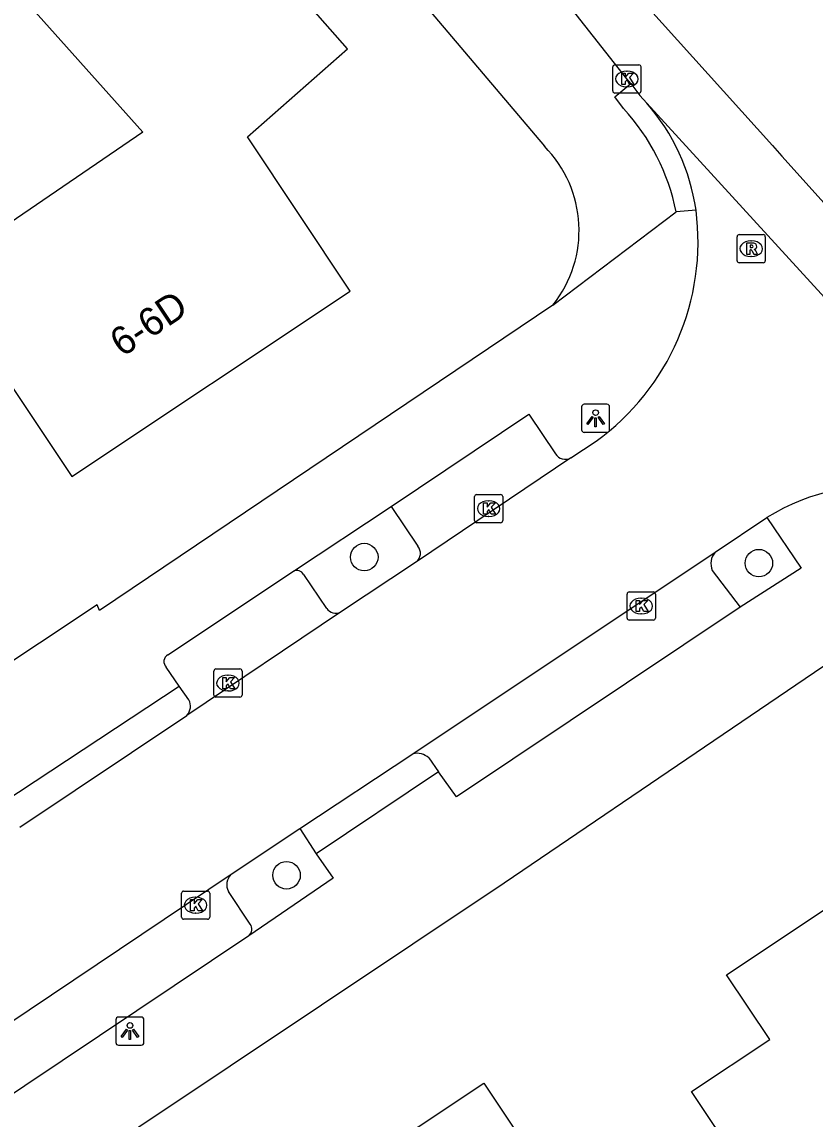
# Model space of a CAD drawing. Extents: x 161354 to 161876, y 382161 to 382804.
# Drawn here: x 161609.6 to 161637.75, y 382619.62 to 382658.57 of the extents above; entities that cross this region are included whole.
import ezdxf

# ---------------------------------------------------------------- set-up
doc = ezdxf.new("R2010")
doc.units = 0
for name, color, linetype in [('IMGEO_Boom', 7, 'Continuous'), ('IMGEO_Fietspad_gesloten', 7, 'Continuous'), ('IMGEO_Kolk', 7, 'Continuous'), ('IMGEO_Lichtpunt', 7, 'Continuous'), ('IMGEO_Pand', 7, 'Continuous'), ('IMGEO_Pand_nummerreeks', 7, 'Continuous'), ('IMGEO_Parkeervlak_open', 7, 'Continuous'), ('IMGEO_Rijbaan_lokaal_gesloten', 7, 'Continuous'), ('IMGEO_Rijbaan_lokaal_open', 7, 'Continuous'), ('IMGEO_Rioolput', 7, 'Continuous'), ('IMGEO_Voetpad_open', 7, 'Continuous')]:
    doc.layers.add(name, color=color, linetype=linetype)

msp = doc.modelspace()

# ---------------------------------------------------------------- linework, layer by layer
at = {"layer": 'IMGEO_Boom'}
for centre in [(161621.754, 382639.57), (161635.76, 382639.355), (161618.995, 382628.273)]:
    msp.add_circle(centre, 0.489, dxfattribs=at)
at = {"layer": 'IMGEO_Fietspad_gesloten'}
for points in [[(161631.214, 382656.385), (161631.077, 382656.546), (161628.402, 382659.955), (161626.262, 382662.585), (161622.699, 382666.884), (161617.707, 382672.442), (161614.343, 382676.276)], [(161631.214, 382656.385), (161631.541, 382655.956), (161631.782, 382655.692)]]:
    msp.add_lwpolyline(points, dxfattribs=at)
at = {"layer": 'IMGEO_Kolk'}
for p, q in [((161630.576, 382656.12), (161630.576, 382656.972)), ((161630.651, 382657.046), (161631.503, 382657.046)), ((161631.064, 382656.826), (161631.089, 382656.826)), ((161631.577, 382656.972), (161631.577, 382656.12)), ((161631.503, 382656.046), (161630.651, 382656.046)), ((161631.087, 382656.266), (161631.062, 382656.266)), ((161625.669, 382640.865), (161625.669, 382641.717)), ((161625.744, 382641.791), (161626.596, 382641.791)), ((161626.157, 382641.571), (161626.182, 382641.571)), ((161626.67, 382641.717), (161626.67, 382640.865)), ((161626.596, 382640.791), (161625.744, 382640.791)), ((161626.18, 382641.011), (161626.155, 382641.011)), ((161631.085, 382637.407), (161631.085, 382638.259)), ((161631.16, 382638.333), (161632.012, 382638.333)), ((161631.573, 382638.113), (161631.598, 382638.113)), ((161632.086, 382638.259), (161632.086, 382637.407)), ((161632.012, 382637.333), (161631.16, 382637.333)), ((161631.596, 382637.553), (161631.571, 382637.553)), ((161616.415, 382634.671), (161616.415, 382635.523)), ((161616.49, 382635.597), (161617.342, 382635.597)), ((161616.903, 382635.377), (161616.928, 382635.377)), ((161617.416, 382635.523), (161617.416, 382634.671)), ((161617.342, 382634.597), (161616.49, 382634.597)), ((161616.926, 382634.817), (161616.901, 382634.817)), ((161615.268, 382626.786), (161615.268, 382627.638)), ((161615.343, 382627.712), (161616.195, 382627.712)), ((161616.269, 382627.638), (161616.269, 382626.786)), ((161615.756, 382627.492), (161615.781, 382627.492)), ((161615.779, 382626.932), (161615.754, 382626.932)), ((161616.195, 382626.712), (161615.343, 382626.712))]:
    msp.add_line(p, q, dxfattribs=at)
for points in [[(161630.576, 382656.12), (161630.576, 382656.972)], [(161630.651, 382657.046), (161631.503, 382657.046)], [(161630.897, 382656.746), (161631.02, 382656.746), (161631.02, 382656.595), (161631.15, 382656.746), (161631.314, 382656.746), (161631.168, 382656.595), (161631.321, 382656.346), (161631.169, 382656.346), (161631.084, 382656.51), (161631.02, 382656.443), (161631.02, 382656.346), (161630.897, 382656.346), (161630.897, 382656.746)], [(161631.577, 382656.972), (161631.577, 382656.12)], [(161631.503, 382656.046), (161630.651, 382656.046)], [(161625.669, 382640.865), (161625.669, 382641.717)], [(161625.744, 382641.791), (161626.596, 382641.791)], [(161626.67, 382641.717), (161626.67, 382640.865)], [(161625.99, 382641.491), (161626.113, 382641.491), (161626.113, 382641.34), (161626.243, 382641.491), (161626.407, 382641.491), (161626.261, 382641.34), (161626.414, 382641.091), (161626.262, 382641.091), (161626.177, 382641.255), (161626.113, 382641.188), (161626.113, 382641.091), (161625.99, 382641.091), (161625.99, 382641.491)], [(161626.596, 382640.791), (161625.744, 382640.791)], [(161631.085, 382637.407), (161631.085, 382638.259)], [(161631.16, 382638.333), (161632.012, 382638.333)], [(161632.086, 382638.259), (161632.086, 382637.407)], [(161631.406, 382638.033), (161631.529, 382638.033), (161631.529, 382637.882), (161631.659, 382638.033), (161631.823, 382638.033), (161631.677, 382637.882), (161631.83, 382637.633), (161631.678, 382637.633), (161631.593, 382637.797), (161631.529, 382637.73), (161631.529, 382637.633), (161631.406, 382637.633), (161631.406, 382638.033)], [(161632.012, 382637.333), (161631.16, 382637.333)], [(161616.415, 382634.671), (161616.415, 382635.523)], [(161616.49, 382635.597), (161617.342, 382635.597)], [(161617.416, 382635.523), (161617.416, 382634.671)], [(161616.736, 382635.297), (161616.859, 382635.297), (161616.859, 382635.146), (161616.989, 382635.297), (161617.153, 382635.297), (161617.007, 382635.146), (161617.16, 382634.897), (161617.008, 382634.897), (161616.923, 382635.061), (161616.859, 382634.994), (161616.859, 382634.897), (161616.736, 382634.897), (161616.736, 382635.297)], [(161617.342, 382634.597), (161616.49, 382634.597)], [(161615.268, 382626.786), (161615.268, 382627.638)], [(161615.343, 382627.712), (161616.195, 382627.712)], [(161616.269, 382627.638), (161616.269, 382626.786)], [(161615.589, 382627.412), (161615.712, 382627.412), (161615.712, 382627.261), (161615.842, 382627.412), (161616.006, 382627.412), (161615.86, 382627.261), (161616.013, 382627.012), (161615.861, 382627.012), (161615.776, 382627.176), (161615.712, 382627.109), (161615.712, 382627.012), (161615.589, 382627.012), (161615.589, 382627.412)], [(161616.195, 382626.712), (161615.343, 382626.712)]]:
    msp.add_lwpolyline(points, dxfattribs=at)
for centre, start, end in [((161630.653, 382656.97), 91.552, 178.448), ((161630.653, 382656.97), 91.552, 178.448), ((161631.501, 382656.97), 1.552, 88.448), ((161631.501, 382656.97), 1.552, 88.448), ((161630.653, 382656.122), 181.552, 268.448), ((161630.653, 382656.122), 181.552, 268.448), ((161631.501, 382656.122), 271.552, 358.448), ((161631.501, 382656.122), 271.552, 358.448), ((161625.746, 382641.715), 91.552, 178.448), ((161625.746, 382641.715), 91.552, 178.448), ((161626.594, 382641.715), 1.552, 88.448), ((161626.594, 382641.715), 1.552, 88.448), ((161625.746, 382640.867), 181.552, 268.448), ((161625.746, 382640.867), 181.552, 268.448), ((161626.594, 382640.867), 271.552, 358.448), ((161626.594, 382640.867), 271.552, 358.448), ((161631.162, 382638.257), 91.552, 178.448), ((161631.162, 382638.257), 91.552, 178.448), ((161632.01, 382638.257), 1.552, 88.448), ((161632.01, 382638.257), 1.552, 88.448), ((161631.162, 382637.409), 181.552, 268.448), ((161631.162, 382637.409), 181.552, 268.448), ((161632.01, 382637.409), 271.552, 358.448), ((161632.01, 382637.409), 271.552, 358.448), ((161616.492, 382635.521), 91.552, 178.448), ((161616.492, 382635.521), 91.552, 178.448), ((161617.34, 382635.521), 1.552, 88.448), ((161617.34, 382635.521), 1.552, 88.448), ((161616.492, 382634.673), 181.552, 268.448), ((161616.492, 382634.673), 181.552, 268.448), ((161617.34, 382634.673), 271.552, 358.448), ((161617.34, 382634.673), 271.552, 358.448), ((161615.345, 382627.636), 91.552, 178.448), ((161615.345, 382627.636), 91.552, 178.448), ((161616.193, 382627.636), 1.552, 88.448), ((161616.193, 382627.636), 1.552, 88.448), ((161615.345, 382626.788), 181.552, 268.448), ((161615.345, 382626.788), 181.552, 268.448), ((161616.193, 382626.788), 271.552, 358.448), ((161616.193, 382626.788), 271.552, 358.448)]:
    msp.add_arc(centre, 0.0765, start, end, dxfattribs=at)
for centre, major_axis, ratio, start_param, end_param in [((161631.063, 382656.546), (-0.387, 0.002), 0.722429, 4.712389, 7.853982), ((161631.088, 382656.546), (-0.39, 0.002), 0.717154, 1.570796, 4.712389), ((161626.156, 382641.291), (-0.387, 0.002), 0.722429, 4.712389, 7.853982), ((161626.181, 382641.291), (-0.39, 0.002), 0.717154, 1.570796, 4.712389), ((161631.572, 382637.833), (-0.387, 0.002), 0.722429, 4.712389, 7.853982), ((161631.597, 382637.833), (-0.39, 0.002), 0.717154, 1.570796, 4.712389), ((161616.902, 382635.097), (-0.387, 0.002), 0.722429, 4.712389, 7.853982), ((161616.927, 382635.097), (-0.39, 0.002), 0.717154, 1.570796, 4.712389), ((161615.755, 382627.212), (-0.387, 0.002), 0.722429, 4.712389, 7.853982), ((161615.78, 382627.212), (-0.39, 0.002), 0.717154, 1.570796, 4.712389)]:
    msp.add_ellipse(centre, major_axis=major_axis, ratio=ratio, start_param=start_param, end_param=end_param, dxfattribs=at)
at = {"layer": 'IMGEO_Lichtpunt'}
for p, q in [((161629.468, 382644.901), (161629.468, 382644.094)), ((161629.468, 382644.901), (161629.468, 382644.094)), ((161630.37, 382644.996), (161629.562, 382644.996)), ((161630.37, 382644.996), (161629.562, 382644.996)), ((161630.464, 382644.094), (161630.464, 382644.901)), ((161630.464, 382644.094), (161630.464, 382644.901)), ((161629.562, 382644), (161630.37, 382644)), ((161629.562, 382644), (161630.37, 382644)), ((161613.841, 382623.238), (161613.033, 382623.238)), ((161613.841, 382623.238), (161613.033, 382623.238)), ((161612.939, 382623.143), (161612.939, 382622.336)), ((161612.939, 382623.143), (161612.939, 382622.336)), ((161613.935, 382622.336), (161613.935, 382623.143)), ((161613.935, 382622.336), (161613.935, 382623.143)), ((161613.033, 382622.242), (161613.841, 382622.242)), ((161613.033, 382622.242), (161613.841, 382622.242))]:
    msp.add_line(p, q, dxfattribs=at)
for points in [[(161629.842, 382644.565), (161629.881, 382644.537), (161629.693, 382644.275), (161629.655, 382644.302), (161629.842, 382644.565)], [(161629.944, 382644.517), (161629.991, 382644.517), (161629.991, 382644.195), (161629.944, 382644.195), (161629.944, 382644.517)], [(161630.054, 382644.537), (161630.092, 382644.564), (161630.279, 382644.302), (161630.24, 382644.274), (161630.054, 382644.537)], [(161613.313, 382622.807), (161613.352, 382622.779), (161613.164, 382622.517), (161613.126, 382622.544), (161613.313, 382622.807)], [(161613.415, 382622.759), (161613.462, 382622.759), (161613.462, 382622.437), (161613.415, 382622.437), (161613.415, 382622.759)], [(161613.525, 382622.779), (161613.563, 382622.806), (161613.75, 382622.544), (161613.711, 382622.516), (161613.525, 382622.779)]]:
    msp.add_lwpolyline(points, dxfattribs=at)
for centre in [(161629.967, 382644.699), (161613.438, 382622.941)]:
    msp.add_circle(centre, 0.0994, dxfattribs=at)
for centre, start, end in [((161629.562, 382644.901), 90, 180), ((161629.562, 382644.901), 90, 180), ((161630.37, 382644.901), 0, 90), ((161630.37, 382644.901), 0, 90), ((161629.562, 382644.094), 180, 270), ((161629.562, 382644.094), 180, 270), ((161630.37, 382644.094), 270, 0), ((161630.37, 382644.094), 270, 360), ((161613.033, 382623.143), 90, 180), ((161613.033, 382623.143), 90, 180), ((161613.841, 382623.143), 0, 90), ((161613.841, 382623.143), 0, 90), ((161613.033, 382622.336), 180, 270), ((161613.033, 382622.336), 180, 270), ((161613.841, 382622.336), 270, 0), ((161613.841, 382622.336), 270, 360)]:
    msp.add_arc(centre, 0.0946, start, end, dxfattribs=at)
at = {"layer": 'IMGEO_Pand'}
for points in [[(161608.598, 382646.589), (161611.371, 382642.428), (161621.256, 382649.017), (161617.611, 382654.487), (161621.16, 382657.617), (161605.587, 382675.281), (161601.837, 382671.975), (161599.917, 382670.282), (161613.901, 382654.655), (161606.558, 382649.651), (161608.598, 382646.589)], [(161632.808, 382613.004), (161636.704, 382615.596), (161633.373, 382620.601), (161636.145, 382622.446), (161634.617, 382624.742), (161643.428, 382630.605), (161645.338, 382627.735), (161645.942, 382628.137), (161648.492, 382624.305), (161648.516, 382623.924), (161646.628, 382622.668), (161652.605, 382613.685), (161655.144, 382615.375), (161658.302, 382610.63), (161655.763, 382608.94), (161651.601, 382606.171), (161643.724, 382600.93), (161640.118, 382606.349), (161643.044, 382608.296), (161639.351, 382613.846), (161634.428, 382610.57)], [(161607.344, 382608.485), (161625.993, 382620.895), (161631.724, 382612.283), (161632.808, 382613.004)]]:
    msp.add_lwpolyline(points, dxfattribs=at)
at = {"layer": 'IMGEO_Parkeervlak_open'}
for points in [[(161622.714, 382641.371), (161623.66, 382639.954)], [(161619.603, 382638.947), (161620.42, 382637.75)], [(161634.107, 382639.095), (161635.101, 382637.794)], [(161617.707, 382626.542), (161616.937, 382627.698)]]:
    msp.add_lwpolyline(points, dxfattribs=at)
for centre, radius, start, end in [((161623.354, 382639.703), 0.395, 309.5117, 39.3937), ((161634.687, 382639.336), 0.629, 139.4269, 202.5645), ((161619.365, 382638.829), 0.266, 26.4762, 117.1333), ((161620.738, 382637.952), 0.376, 212.416, 298.1539), ((161617.384, 382627.941), 0.509, 133.8819, 208.5976), ((161617.461, 382626.363), 0.305, 309.6025, 36.0794)]:
    msp.add_arc(centre, radius, start, end, dxfattribs=at)
at = {"layer": 'IMGEO_Rijbaan_lokaal_gesloten'}
msp.add_lwpolyline([(161575.378, 382721.548), (161577.619, 382719.049), (161589.767, 382705.692), (161601.665, 382692.722), (161616.607, 382676.142), (161624.391, 382667.348), (161636.242, 382654.182), (161636.579, 382653.807), (161653.899, 382634.564), (161673.989, 382613.712), (161706.007, 382577.787), (161705.643, 382575.646)], dxfattribs=at)
at = {"layer": 'IMGEO_Rijbaan_lokaal_open'}
for points in [[(161631.782, 382655.692), (161639.863, 382646.847), (161645.871, 382640.073)], [(161629.082, 382643.096), (161629.984, 382643.685)], [(161629.082, 382643.096), (161623.606, 382639.398)], [(161634.21, 382639.745), (161636.042, 382640.978)], [(161623.482, 382632.585), (161634.21, 382639.745)], [(161623.606, 382639.398), (161620.915, 382637.62)], [(161620.915, 382637.62), (161615.453, 382633.951)], [(161609.534, 382629.982), (161615.453, 382633.951)], [(161619.464, 382629.933), (161623.482, 382632.585)], [(161617.031, 382628.308), (161619.464, 382629.933)], [(161606.677, 382621.365), (161617.031, 382628.308)]]:
    msp.add_lwpolyline(points, dxfattribs=at)
for centre, radius, start, end in [((161626.175, 382650.809), 7.435, 8.3664, 41.0519), ((161624.863, 382650.768), 8.74, 305.8648, 7.3829), ((161640.338, 382633.811), 8.356, 48.5361, 120.9426)]:
    msp.add_arc(centre, radius, start, end, dxfattribs=at)
at = {"layer": 'IMGEO_Rioolput'}
for p, q in [((161634.988, 382650.094), (161634.988, 382650.946)), ((161635.063, 382651.02), (161635.915, 382651.02)), ((161635.989, 382650.946), (161635.989, 382650.094)), ((161635.476, 382650.8), (161635.501, 382650.8)), ((161635.499, 382650.24), (161635.474, 382650.24)), ((161635.915, 382650.02), (161635.063, 382650.02))]:
    msp.add_line(p, q, dxfattribs=at)
for points in [[(161634.988, 382650.094), (161634.988, 382650.946)], [(161635.063, 382651.02), (161635.915, 382651.02)], [(161635.989, 382650.946), (161635.989, 382650.094)], [(161635.577, 382650.718), (161635.325, 382650.72), (161635.325, 382650.32)], [(161635.503, 382650.639), (161635.449, 382650.639), (161635.449, 382650.558)], [(161635.449, 382650.558), (161635.501, 382650.558)], [(161635.325, 382650.32), (161635.449, 382650.32), (161635.449, 382650.482), (161635.46, 382650.482)], [(161635.507, 382650.453), (161635.578, 382650.32), (161635.718, 382650.32), (161635.653, 382650.446)], [(161635.915, 382650.02), (161635.063, 382650.02)]]:
    msp.add_lwpolyline(points, dxfattribs=at)
for centre, radius, start, end in [((161635.065, 382650.944), 0.0765, 91.552, 178.448), ((161635.065, 382650.944), 0.0765, 91.552, 178.448), ((161635.913, 382650.944), 0.0765, 1.552, 88.448), ((161635.913, 382650.944), 0.0765, 1.552, 88.448), ((161635.485, 382650.747), 0.19, 274.7715, 282.9687), ((161635.509, 382650.543), 0.0964, 77.0061, 93.1865), ((161635.523, 382650.6), 0.0378, 276.6634, 79.6772), ((161635.576, 382650.608), 0.109, 350.3612, 89.416), ((161635.574, 382650.608), 0.112, 277.5842, 350.9817), ((161635.459, 382650.429), 0.0533, 26.0293, 88.6989), ((161635.558, 382650.393), 0.108, 29.5134, 73.7905), ((161635.065, 382650.096), 0.0765, 181.552, 268.448), ((161635.065, 382650.096), 0.0765, 181.552, 268.448), ((161635.913, 382650.096), 0.0765, 271.552, 358.448), ((161635.913, 382650.096), 0.0765, 271.552, 358.448)]:
    msp.add_arc(centre, radius, start, end, dxfattribs=at)
for centre, major_axis, ratio, start_param, end_param in [((161635.475, 382650.52), (-0.387, 0.002), 0.722429, 4.712389, 7.853982), ((161635.5, 382650.52), (-0.39, 0.002), 0.717154, 1.570796, 4.712389)]:
    msp.add_ellipse(centre, major_axis=major_axis, ratio=ratio, start_param=start_param, end_param=end_param, dxfattribs=at)
at = {"layer": 'IMGEO_Voetpad_open'}
for points in [[(161555.239, 382731.179), (161568.031, 382720.568), (161571.485, 382717.274), (161591.856, 382694.988), (161613.021, 382671.42), (161613.19, 382671.62), (161617.321, 382666.942), (161628.148, 382654.156)], [(161630.957, 382655.494), (161630.647, 382655.913), (161631.214, 382656.385)], [(161628.452, 382648.518), (161632.827, 382651.824)], [(161633.531, 382651.891), (161632.827, 382651.824)], [(161628.452, 382648.518), (161612.356, 382637.679), (161612.276, 382637.879), (161577.471, 382614.736), (161574.373, 382612.676), (161556.508, 382600.797), (161530.719, 382583.477), (161519.986, 382585.99)], [(161622.714, 382641.371), (161627.594, 382644.645), (161628.547, 382643.241)], [(161619.244, 382639.065), (161622.714, 382641.371)], [(161636.042, 382640.978), (161637.263, 382639.172), (161635.101, 382637.794)], [(161614.786, 382636.096), (161619.244, 382639.065)], [(161642.272, 382638.554), (161626.724, 382627.988), (161591.014, 382604.147)], [(161635.101, 382637.794), (161625.023, 382631.053), (161624.388, 382631.946)], [(161615.188, 382634.992), (161614.729, 382635.667)], [(161608.932, 382630.859), (161615.188, 382634.992)], [(161615.531, 382634.502), (161615.188, 382634.992)], [(161624.045, 382632.438), (161624.388, 382631.946)], [(161624.388, 382631.946), (161620.048, 382629.035)], [(161619.464, 382629.933), (161620.048, 382629.035)], [(161620.048, 382629.035), (161620.647, 382628.172), (161617.655, 382626.128)], [(161617.655, 382626.128), (161608.366, 382619.905)]]:
    msp.add_lwpolyline(points, dxfattribs=at)
for centre, radius, start, end in [((161625.333, 382650.317), 7.644, 11.3715, 42.6295), ((161625.133, 382651.166), 4.246, 321.4093, 44.7635), ((161628.884, 382643.425), 0.384, 208.6427, 301.0284), ((161614.908, 382635.861), 0.264, 117.5168, 227.3464), ((161615.121, 382634.279), 0.466, 315.3101, 28.5753), ((161623.631, 382632.002), 0.601, 46.4282, 104.3052)]:
    msp.add_arc(centre, radius, start, end, dxfattribs=at)

# ---------------------------------------------------------------- texts
at = {"layer": 'IMGEO_Pand_nummerreeks'}
msp.add_text('6-6D', height=1, rotation=33.6861, dxfattribs=at).set_placement((161613.165, 382646.653))

doc.saveas('drawing.dxf')
